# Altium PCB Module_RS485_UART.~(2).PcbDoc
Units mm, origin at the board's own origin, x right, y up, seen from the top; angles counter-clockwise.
Board outline 70 x 25 mm, 2 copper layers (Top Layer, Bottom Layer); 16 components, 16 nets, 60 pads, 0 vias.
Unrouted connection lines stored in the file: 44.
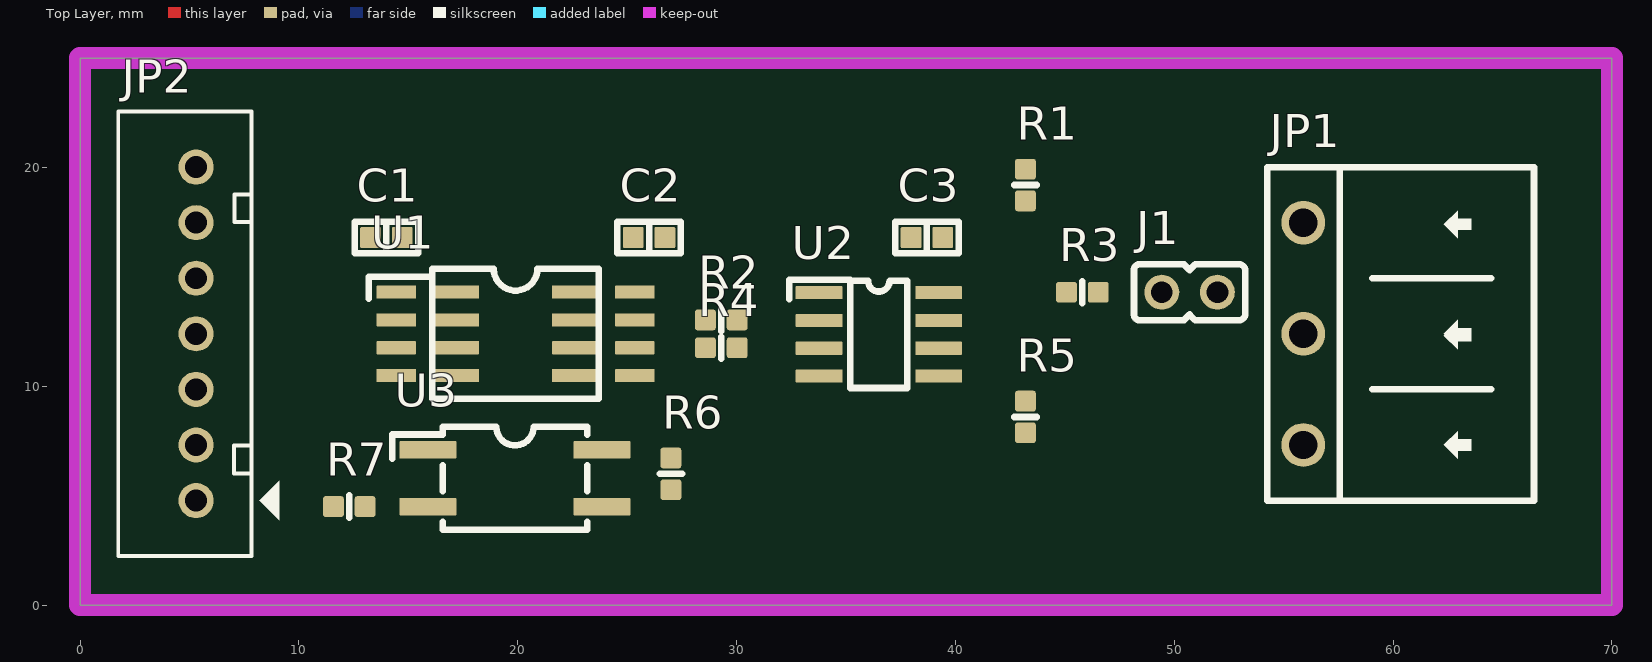
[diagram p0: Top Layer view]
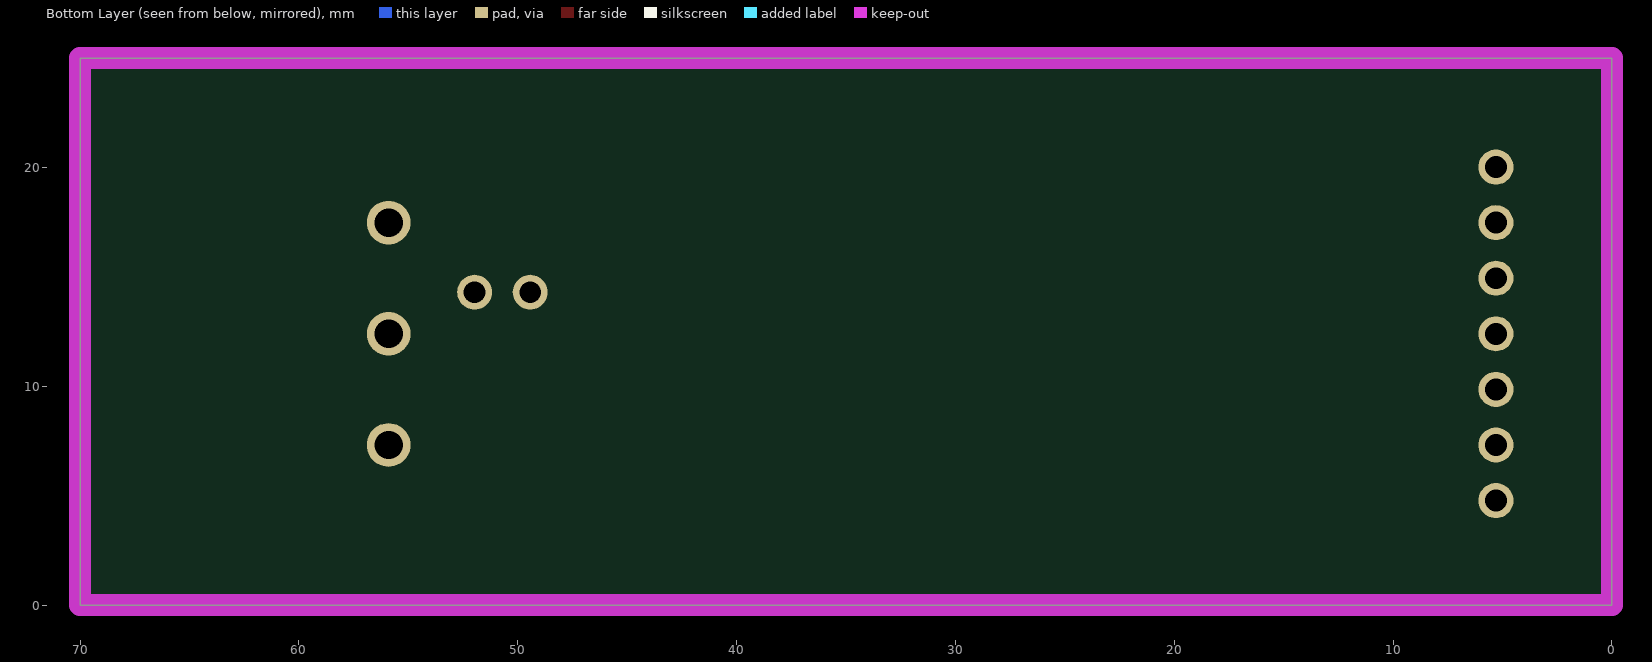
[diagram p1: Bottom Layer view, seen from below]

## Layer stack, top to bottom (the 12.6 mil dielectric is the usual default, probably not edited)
Top Solder: solder mask 0.0102, Solder Resist, Dk 3.5
Top Layer: signal copper 0.0356
Dielectric 1: dielectric 0.32, FR-4, Dk 4.8
Bottom Layer: signal copper 0.0356
Bottom Solder: solder mask 0.0102, Solder Resist, Dk 3.5

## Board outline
0,0 70,0 70,25 0,25

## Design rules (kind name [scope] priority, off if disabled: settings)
Clearance [All] p1: gap=0.254 ignorepadtopadclearanceinfootprint=FALSE except(0: Arc-Hole Track-Hole SMDPad-Hole THPad-Hole Via-Hole Fill-Hole Poly-Hole Region-Hole Text-Hole)
PolygonConnect [All] p1: connectstyle=Relief reliefconductorwidth=0.254 reliefentries=4 polygonreliefangle="90 Angle" airgapwidth=0.254
RoutingVias [All] p1: holewidth=0.711 width=1.27 viastyle="Through Hole" minholewidth=0.711 minwidth=1.27 maxholewidth=0.711 maxwidth=1.27
SolderMaskExpansion [All] p1: expansion=0.102 istentingtop=FALSE
Width [All] p1: maxlimit=0.254 minlimit=0.254 preferedwidth=0.254
30 further rules are at their usual default settings.

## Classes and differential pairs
net class Power: 3V3 3V3_MCU GND_MCU GND_P

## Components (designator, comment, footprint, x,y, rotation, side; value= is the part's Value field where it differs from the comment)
C1 "1uF/10V" "Cap Ceramic 0603 SMD" 14,16.8 r0 top
C2 "1uF/10V" "Cap Ceramic 0603 SMD" 26,16.8 r0 top
C3 "1uF/10V" "Cap Ceramic 0603 SMD" 38.7,16.8 r180 top
J1 "Jumper" Header_2 50.7,14.3 r0 top
JP1 "JP3" 2EDGR-5.08-03P 55.9,12.4 r270 top value="Connector 3"
JP2 "JP7" CON7 5.3,12.4 r90 top value="Connector 7"
R1 "2K2" "Res 0603 SMD_v2" 43.2,19.2 r90 top
R2 "120" "Res 0603 SMD_v2" 29.3,13.035 r180 top
R3 "120" "Res 0603 SMD_v2" 45.8,14.3 r180 top
R4 "120" "Res 0603 SMD_v2" 29.3,11.765 r180 top
R5 "2K2" "Res 0603 SMD_v2" 43.2,8.6 r90 top
R6 "10K" "Res 0603 SMD_v2" 27,6 r90 top
R7 "330" "Res 0603 SMD_v2" 12.3,4.505 r180 top
U1 "ISO7721DR SOIC 8" "ISO7721D SOIC-8 10.9mm" 19.9,12.4 r270 top
U2 "SP3485 SOIC8" "SP3485 SOIC-8 3.9mm" 36.5,12.375 r270 top
U3 "PC817-SOP4" TPC817-4SOP 19.872,5.8 r0 top

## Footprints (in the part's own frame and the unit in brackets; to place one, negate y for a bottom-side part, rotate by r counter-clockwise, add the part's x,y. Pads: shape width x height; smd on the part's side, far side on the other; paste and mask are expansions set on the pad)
2EDGR-5.08-03P [mm] "Terminal Block 3 Chân 5.08 Chân Cong 3EDG-5.08-3P-L"
  round 2 hole 1.3 mask+0.1: 1(-5.08,0) 2(0,0) 3(5.08,0)
  silkscreen extent -7.62,-1.66 7.62,10.54, body extent -7.62,-1.52 7.62,10.58, height 8.1
"Cap Ceramic 0603 SMD" [mm] "Reflow Soldering"
  rrect10% 0.95x0.95 smd mask+0.1: 1(-0.725,0) 2(0.725,0)
  silkscreen extent -1.45,-0.72 1.45,0.73, body extent -0.8,-0.4 0.8,0.4, height 0.85
CON7 [mm] "CON7"
  round 1.6 hole 1 mask+0.1: 1(-7.62,0) 2(-5.08,0) 3(-2.54,0) 4(0,0) 5(2.54,0) 6(5.08,0) 7(7.62,0)
  silkscreen extent -10.16,-3.8 10.16,3.56, body extent -10.05,-2.29 10.05,3.41, height 7
Header_2 [mm] "Connector DIP, 2Pin_2.54mm"
  round 1.6 hole 1 mask+0.1: 1(-1.27,0) 2(1.27,0)
  silkscreen extent -2.54,-1.28 2.54,1.28, body extent -2.54,-1.27 2.54,1.27, height 10.1
"ISO7721D SOIC-8 10.9mm" [mm] "SOIC-8 10.9mm"
  rrect10% 0.6x1.8 smd mask+0.07: 1(-1.905,-5.45) 2(-0.635,-5.45) 3(0.635,-5.45) 4(1.905,-5.45) 5(1.905,5.45) 6(0.635,5.45) 7(-0.635,5.45) 8(-1.905,5.45)
  rrect10% 0.6x2.135 smd mask+0.1: 1(-1.905,-2.732) 2(-0.635,-2.732) 3(0.635,-2.732) 4(1.905,-2.732) 5(1.905,2.733) 6(0.635,2.733) 7(-0.635,2.733) 8(-1.905,2.733)
  silkscreen extent -2.98,-6.7 2.98,3.81, body extent -2.45,-3 2.45,3, height 1.75
"Res 0603 SMD_v2" [mm]
  rrect25% 0.95x0.95 smd mask+0.1: 1(-0.725,0) 2(0.725,0)
  silkscreen extent 0,-0.51 0,0.51, body extent -0.8,-0.4 0.8,0.4, height 0.48
"SP3485 SOIC-8 3.9mm" [mm] "8-Pin SOIC 3.9mm Width"
  rrect10% 0.6x2.135 smd mask+0.1: 1(-1.905,-2.732) 2(-0.635,-2.732) 3(0.635,-2.732) 4(1.905,-2.732) 5(1.905,2.733) 6(0.635,2.733) 7(-0.635,2.733) 8(-1.905,2.733)
  silkscreen extent -2.5,-4.1 2.45,1.3, body extent -2.45,-3 2.45,3, height 1.75
TPC817-4SOP [mm] "OPTOISO 5KV TRANS 4SOP"
  rrect10% 2.6x0.8 smd: 1(-3.975,1.295) 2(-3.975,-1.295) 3(3.975,-1.295) 4(3.975,1.295)
  silkscreen extent -5.6,-2.35 3.3,2.35, body extent -3.5,-1.92 3.5,1.93, height 2

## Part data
C1 C2 C3: library part "Cap Ceramic SMD"
J1: "Jumper Wire"
JP1: library part Con3, "Connector 3"
JP2: library part Con7, "Connector 7"
R1 R2 R3 R4 R5 R6 R7: library part 249K/R0805/1%_2, "RES SMD 249K OHM 1% 1/10W 0805", Manufacturer=Yageo, Manufacturer Part Number=RC0603FR-07249KL, Operating Temperature="-55°C ~ 155°C", Package / Case="0603 (1608 Metric)", Power (Watts)="0.1W, 1/10W", Supplier Device Package=0603, Temperature Coefficient=±100ppm/°C, Tolerance=±1%
U1: "ISO772x High-Speed, Robust EMC, Reinforced Dual-Channel Digital Isolators"
U3: library part PC817, "Optoisolator Transistor Output 5000Vrms 1 Channel 4-SOP"

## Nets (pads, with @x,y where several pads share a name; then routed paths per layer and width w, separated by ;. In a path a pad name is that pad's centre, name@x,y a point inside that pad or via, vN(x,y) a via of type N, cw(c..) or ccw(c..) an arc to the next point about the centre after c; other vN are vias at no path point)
3V3: C2.1 C3.1 JP2.7 R1.2 R6.1 U1.8 U2.8
3V3_MCU: C1.1 JP2.6 U1.1 U3.1
CONTROL: R6.2 U2.2 U2.3 U3.4
GND_MCU: C1.2 JP2.4 U1.4
GND_P: C2.2 C3.2 JP1.3 JP2.5 R5.1 U1.5 U2.5 U3.3
MCU_CTRL: JP2.3 R7.2
MCU_RX: JP2.1 U1.2
MCU_TX: JP2.2 U1.3
NetJ1_1: J1.1 R3.1
NetJ1_2: J1.2 JP1.2 R5.2 U2.6
NetJP1_1: JP1.1 R1.1 R3.2 U2.7
NetR2_1: R2.1 U2.1
NetR2_2: R2.2 U1.7
NetR4_1: R4.1 U2.4
NetR4_2: R4.2 U1.6
NetR7_1: R7.1 U3.2

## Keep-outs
Keep-Out Layer:
  the board outline again, w1

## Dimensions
0,25 to 0,0 on Mechanical 10
0,25 to 70,25 on Mechanical 10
